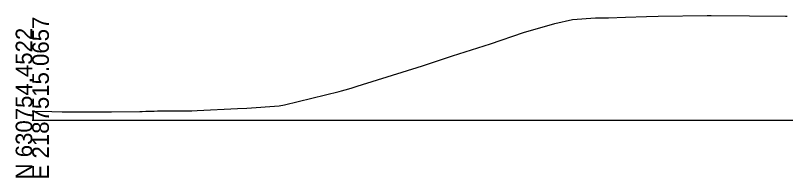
# Model space of a CAD drawing. Extents: x -26 to 2903, y -10 to 63.
# Drawn here: x 1297.2 to 1427, y -9.7 to 17.7 of the extents above; entities that cross this region are included whole.
import ezdxf

# ---------------------------------------------------------------- set-up
doc = ezdxf.new("R2010")
doc.units = 0
for name, color, linetype in [('Default', 7, 'Continuous'), ('Exist Cross Section Cell', 7, 'Continuous'), ('Exist XS Ground Line', 7, 'Continuous')]:
    doc.layers.add(name, color=color, linetype=linetype)

msp = doc.modelspace()

# ---------------------------------------------------------------- linework, layer by layer
at = {"layer": 'Exist Cross Section Cell'}
msp.add_line((1300, 0), (1450, 0), dxfattribs=at)
at = {"layer": 'Exist XS Ground Line'}
for p, q in [((1388.11, 16.31), (1391.06, 17.01)), ((1391.06, 17.01), (1394.95, 17.29)), ((1394.95, 17.29), (1397.15, 17.31)), ((1397.15, 17.31), (1400.05, 17.38)), ((1400.05, 17.38), (1403.56, 17.5)), ((1403.56, 17.5), (1405.53, 17.54)), ((1405.53, 17.54), (1413.81, 17.7)), ((1413.81, 17.7), (1414.45, 17.69)), ((1414.45, 17.69), (1420.92, 17.64)), ((1420.92, 17.64), (1426.98, 17.57)), ((1426.98, 17.57), (1427.3, 17.57)), ((1382.84, 14.8), (1388.11, 16.31)), ((1377.26, 12.9), (1382.84, 14.8)), ((1370.87, 10.85), (1377.26, 12.9)), ((1365.81, 9.18), (1370.87, 10.85)), ((1354.8, 5.74), (1365.81, 9.18)), ((1352.75, 5.14), (1353.75, 5.4)), ((1353.75, 5.4), (1354.8, 5.74)), ((1342.51, 2.61), (1351.77, 4.87)), ((1351.77, 4.87), (1352.12, 4.94)), ((1352.12, 4.94), (1352.75, 5.14)), ((1341.63, 2.4), (1342.51, 2.61)), ((1300, 1.51), (1303.3, 1.46)), ((1303.3, 1.46), (1305.06, 1.43)), ((1305.06, 1.43), (1307.92, 1.42)), ((1307.92, 1.42), (1313.34, 1.42)), ((1313.34, 1.42), (1318.13, 1.45)), ((1318.13, 1.45), (1318.51, 1.48)), ((1318.51, 1.48), (1319.16, 1.5)), ((1319.16, 1.5), (1320.53, 1.55)), ((1320.53, 1.55), (1321.11, 1.58)), ((1321.11, 1.58), (1321.51, 1.58)), ((1321.51, 1.58), (1326.91, 1.6)), ((1326.91, 1.6), (1327.81, 1.62)), ((1327.81, 1.62), (1334.59, 1.95)), ((1334.59, 1.95), (1336.17, 2.04)), ((1336.17, 2.04), (1341.63, 2.4))]:
    msp.add_line(p, q, dxfattribs=at)

# ---------------------------------------------------------------- texts
at = {"layer": 'Default'}
msp.add_text('-', height=0.0001, dxfattribs=at).set_placement((1300, 0))
at = {"layer": 'Exist Cross Section Cell'}
for s, p in [('E 2187515.0657', (1302.8, -10)), ('N 630754.4522', (1300, -10))]:
    msp.add_text(s, height=2.8, rotation=90, dxfattribs=at).set_placement(p)

doc.saveas('drawing.dxf')
